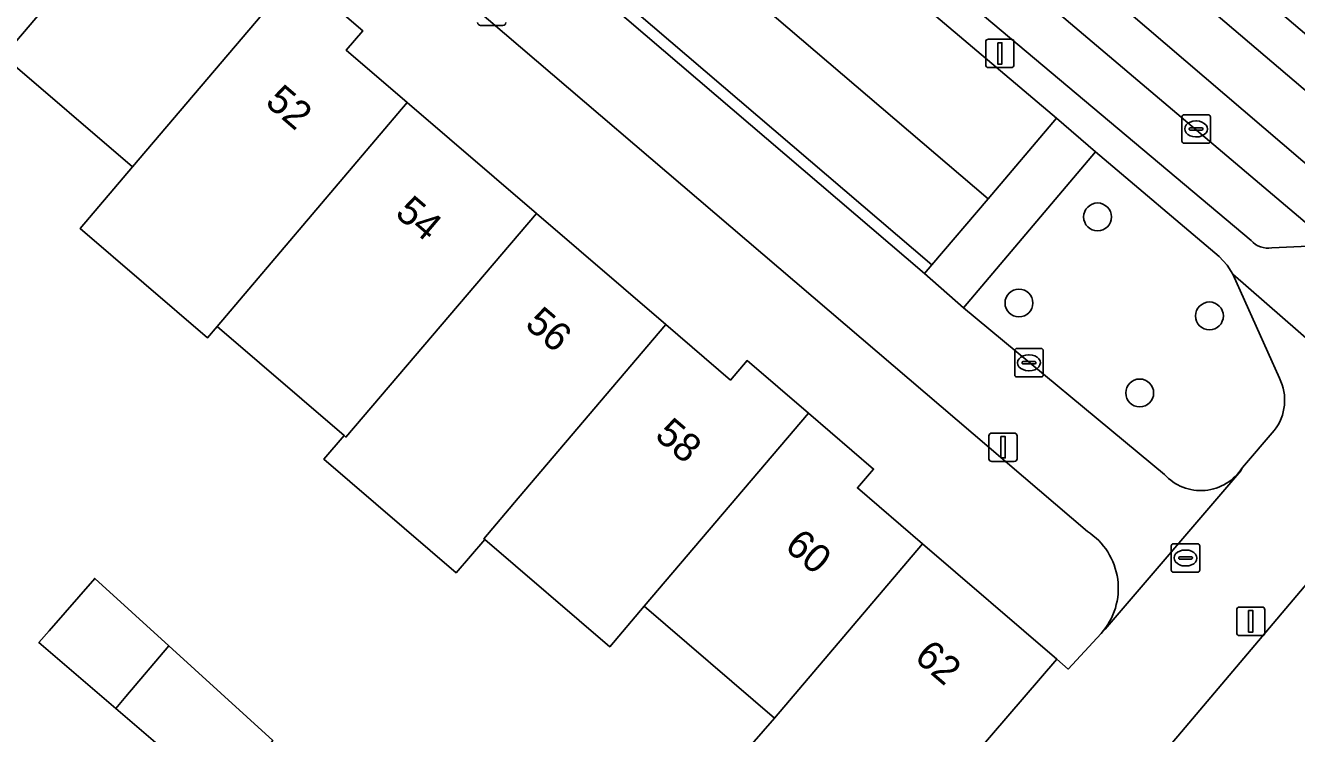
# Model space of a CAD drawing. Extents: x 162523 to 163266, y 381230 to 382050.
# Drawn here: x 163035.02 to 163079.66, y 381775.7 to 381800.56 of the extents above; entities that cross this region are included whole.
import ezdxf

# ---------------------------------------------------------------- set-up
doc = ezdxf.new("R2010")
doc.units = 0
for name, color, linetype in [('IMGEO_Boom', 7, 'Continuous'), ('IMGEO_Brandkraan', 7, 'Continuous'), ('IMGEO_Erf', 7, 'Continuous'), ('IMGEO_Groenvoorziening', 7, 'Continuous'), ('IMGEO_Haag', 7, 'Continuous'), ('IMGEO_Kolk', 7, 'Continuous'), ('IMGEO_Lichtmast', 7, 'Continuous'), ('IMGEO_Pand', 7, 'Continuous'), ('IMGEO_Pand_nummerreeks', 7, 'Continuous'), ('IMGEO_Parkeervlak_open', 7, 'Continuous'), ('IMGEO_Rijbaan_lokaal_gesloten', 7, 'Continuous'), ('IMGEO_Rijbaan_lokaal_open', 7, 'Continuous'), ('IMGEO_Verkeerseiland_gesloten', 7, 'Continuous'), ('IMGEO_Voetpad_open', 7, 'Continuous')]:
    doc.layers.add(name, color=color, linetype=linetype)

msp = doc.modelspace()

# ---------------------------------------------------------------- linework, layer by layer
at = {"layer": 'IMGEO_Boom'}
for centre in [(163072.674, 381793.839), (163069.913, 381790.816), (163076.605, 381790.363), (163074.155, 381787.658)]:
    msp.add_circle(centre, 0.489, dxfattribs=at)
at = {"layer": 'IMGEO_Brandkraan'}
for p, q in [((163075.339, 381782.364), (163076.191, 381782.364)), ((163075.264, 381781.438), (163075.264, 381782.29)), ((163075.566, 381781.907), (163075.964, 381781.907)), ((163075.752, 381782.144), (163075.777, 381782.144)), ((163076.265, 381782.29), (163076.265, 381781.438)), ((163075.523, 381781.858), (163075.523, 381781.87)), ((163075.961, 381781.821), (163075.563, 381781.821)), ((163075.775, 381781.584), (163075.75, 381781.584)), ((163076.007, 381781.87), (163076.007, 381781.858)), ((163076.191, 381781.364), (163075.339, 381781.364))]:
    msp.add_line(p, q, dxfattribs=at)
for points in [[(163075.339, 381782.364), (163076.191, 381782.364)], [(163075.264, 381781.438), (163075.264, 381782.29)], [(163076.265, 381782.29), (163076.265, 381781.438)], [(163076.191, 381781.364), (163075.339, 381781.364)]]:
    msp.add_lwpolyline(points, dxfattribs=at)
for centre, radius, start, end in [((163075.341, 381782.288), 0.0765, 91.552, 178.448), ((163075.341, 381782.288), 0.0765, 91.552, 178.448), ((163076.189, 381782.288), 0.0765, 1.552, 88.448), ((163076.189, 381782.288), 0.0765, 1.552, 88.448), ((163075.563, 381781.867), 0.0403, 85.8775, 175.7526), ((163075.968, 381781.869), 0.0386, 1.7309, 96.639), ((163075.56, 381781.857), 0.0366, 178.938, 274.7102), ((163075.964, 381781.864), 0.043, 264.8664, 352.4533), ((163075.341, 381781.44), 0.0765, 181.552, 268.448), ((163075.341, 381781.44), 0.0765, 181.552, 268.448), ((163076.189, 381781.44), 0.0765, 271.552, 358.448), ((163076.189, 381781.44), 0.0765, 271.552, 358.448)]:
    msp.add_arc(centre, radius, start, end, dxfattribs=at)
for centre, major_axis, ratio, start_param, end_param in [((163075.751, 381781.864), (-0.387, 0.002), 0.722429, 4.712389, 7.853982), ((163075.776, 381781.864), (-0.39, 0.002), 0.717154, 1.570796, 4.712389)]:
    msp.add_ellipse(centre, major_axis=major_axis, ratio=ratio, start_param=start_param, end_param=end_param, dxfattribs=at)
at = {"layer": 'IMGEO_Erf'}
for points in [[(163072.316, 381782.8), (163039.316, 381810.986)], [(163035.168, 381810.664), (163034.367, 381809.775), (163034.766, 381809.504), (163039.393, 381805.532), (163041.723, 381803.532), (163042.345, 381804.256), (163044.538, 381802.373), (163046.874, 381800.368), (163046.292, 381799.689), (163048.434, 381797.85), (163052.967, 381793.958), (163057.512, 381790.057), (163059.781, 381788.109), (163060.369, 381788.794), (163062.518, 381786.95), (163064.809, 381784.984), (163064.242, 381784.322), (163066.529, 381782.358), (163071.239, 381778.315), (163071.642, 381777.967), (163072.8, 381779.218)], [(163058.939, 381773.505), (163061.326, 381776.24), (163056.75, 381780.169), (163055.541, 381778.749), (163051.151, 381782.517), (163050.146, 381781.346), (163045.507, 381785.328), (163046.22, 381786.159), (163041.754, 381789.992), (163041.415, 381789.593), (163036.944, 381793.432), (163038.781, 381795.595), (163034.252, 381799.483)]]:
    msp.add_lwpolyline(points, dxfattribs=at)
msp.add_lwpolyline([(163038.196, 381776.584), (163035.497, 381778.894), (163035.853, 381779.304), (163037.456, 381781.149), (163040.061, 381778.777), (163043.708, 381775.457), (163041.97, 381773.351)], close=True, dxfattribs=at)
msp.add_arc((163071.021, 381780.801), 2.382, 318.3372, 57.0532, dxfattribs=at)
at = {"layer": 'IMGEO_Groenvoorziening'}
for points in [[(163071.233, 381797.302), (163053.446, 381812.343), (163051.086, 381809.632), (163068.827, 381794.472)], [(163068.827, 381794.472), (163051.086, 381809.632), (163049.09, 381807.34), (163066.858, 381792.157)], [(163066.858, 381792.157), (163049.09, 381807.34), (163048.827, 381807.038), (163066.599, 381791.852)]]:
    msp.add_lwpolyline(points, close=True, dxfattribs=at)
for points in [[(163079.06, 381788.177), (163077.42, 381791.832), (163077.226, 381792.149), (163076.943, 381792.45), (163072.604, 381796.126), (163067.968, 381790.65), (163075.022, 381784.8)], [(163077.759, 381785.04), (163078.877, 381786.336)]]:
    msp.add_lwpolyline(points, dxfattribs=at)
for centre, radius, start, end in [((163077.525, 381787.4), 1.721, 321.8026, 26.844), ((163076.3, 381785.957), 1.724, 222.167, 327.8556)]:
    msp.add_arc(centre, radius, start, end, dxfattribs=at)
at = {"layer": 'IMGEO_Haag'}
msp.add_lwpolyline([(163066.858, 381792.157), (163049.09, 381807.34), (163048.827, 381807.038), (163066.599, 381791.852)], close=True, dxfattribs=at)
at = {"layer": 'IMGEO_Kolk'}
for p, q in [((163075.634, 381796.5), (163075.634, 381797.352)), ((163075.709, 381797.426), (163076.561, 381797.426)), ((163076.122, 381797.206), (163076.147, 381797.206)), ((163076.635, 381797.352), (163076.635, 381796.5)), ((163075.893, 381796.92), (163075.893, 381796.932)), ((163076.331, 381796.883), (163075.933, 381796.883)), ((163075.936, 381796.969), (163076.334, 381796.969)), ((163076.145, 381796.646), (163076.12, 381796.646)), ((163076.377, 381796.932), (163076.377, 381796.92)), ((163076.561, 381796.426), (163075.709, 381796.426)), ((163069.764, 381788.293), (163069.764, 381789.145)), ((163069.839, 381789.219), (163070.691, 381789.219)), ((163070.765, 381789.145), (163070.765, 381788.293)), ((163070.023, 381788.713), (163070.023, 381788.725)), ((163070.461, 381788.676), (163070.063, 381788.676)), ((163070.066, 381788.762), (163070.464, 381788.762)), ((163070.252, 381788.999), (163070.277, 381788.999)), ((163070.507, 381788.725), (163070.507, 381788.713)), ((163070.691, 381788.219), (163069.839, 381788.219)), ((163070.275, 381788.439), (163070.25, 381788.439))]:
    msp.add_line(p, q, dxfattribs=at)
for points in [[(163075.634, 381796.5), (163075.634, 381797.352)], [(163075.709, 381797.426), (163076.561, 381797.426)], [(163076.635, 381797.352), (163076.635, 381796.5)], [(163076.561, 381796.426), (163075.709, 381796.426)], [(163069.764, 381788.293), (163069.764, 381789.145)], [(163069.839, 381789.219), (163070.691, 381789.219)], [(163070.765, 381789.145), (163070.765, 381788.293)], [(163070.691, 381788.219), (163069.839, 381788.219)]]:
    msp.add_lwpolyline(points, dxfattribs=at)
for centre, radius, start, end in [((163075.711, 381797.35), 0.0765, 91.552, 178.448), ((163075.711, 381797.35), 0.0765, 91.552, 178.448), ((163076.559, 381797.35), 0.0765, 1.552, 88.448), ((163076.559, 381797.35), 0.0765, 1.552, 88.448), ((163075.933, 381796.929), 0.0403, 85.8775, 175.7526), ((163075.93, 381796.919), 0.0366, 178.938, 274.7102), ((163076.334, 381796.926), 0.043, 264.8664, 352.4533), ((163076.338, 381796.931), 0.0386, 1.7309, 96.639), ((163075.711, 381796.502), 0.0765, 181.552, 268.448), ((163075.711, 381796.502), 0.0765, 181.552, 268.448), ((163076.559, 381796.502), 0.0765, 271.552, 358.448), ((163076.559, 381796.502), 0.0765, 271.552, 358.448), ((163069.841, 381789.143), 0.0765, 91.552, 178.448), ((163069.841, 381789.143), 0.0765, 91.552, 178.448), ((163070.689, 381789.143), 0.0765, 1.552, 88.448), ((163070.689, 381789.143), 0.0765, 1.552, 88.448), ((163070.063, 381788.722), 0.0403, 85.8775, 175.7526), ((163070.06, 381788.712), 0.0366, 178.938, 274.7102), ((163070.464, 381788.719), 0.043, 264.8664, 352.4533), ((163070.468, 381788.724), 0.0386, 1.7309, 96.639), ((163069.841, 381788.295), 0.0765, 181.552, 268.448), ((163069.841, 381788.295), 0.0765, 181.552, 268.448), ((163070.689, 381788.295), 0.0765, 271.552, 358.448), ((163070.689, 381788.295), 0.0765, 271.552, 358.448)]:
    msp.add_arc(centre, radius, start, end, dxfattribs=at)
for centre, major_axis, ratio, start_param, end_param in [((163076.121, 381796.926), (-0.387, 0.002), 0.722429, 4.712389, 7.853982), ((163076.146, 381796.926), (-0.39, 0.002), 0.717154, 1.570796, 4.712389), ((163070.251, 381788.719), (-0.387, 0.002), 0.722429, 4.712389, 7.853982), ((163070.276, 381788.719), (-0.39, 0.002), 0.717154, 1.570796, 4.712389)]:
    msp.add_ellipse(centre, major_axis=major_axis, ratio=ratio, start_param=start_param, end_param=end_param, dxfattribs=at)
at = {"layer": 'IMGEO_Lichtmast'}
for p, q in [((163051.794, 381800.56), (163051.004, 381800.56)), ((163051.004, 381800.56), (163051.794, 381800.56)), ((163068.747, 381799.179), (163068.747, 381799.979)), ((163068.747, 381799.979), (163068.747, 381799.179)), ((163068.847, 381800.079), (163069.637, 381800.079)), ((163069.637, 381800.079), (163068.847, 381800.079)), ((163069.737, 381799.979), (163069.737, 381799.179)), ((163069.737, 381799.179), (163069.737, 381799.979)), ((163069.637, 381799.079), (163068.847, 381799.079)), ((163068.847, 381799.079), (163069.637, 381799.079)), ((163068.861, 381785.35), (163068.861, 381786.15)), ((163068.861, 381786.15), (163068.861, 381785.35)), ((163068.961, 381786.25), (163069.751, 381786.25)), ((163069.751, 381786.25), (163068.961, 381786.25)), ((163069.851, 381786.15), (163069.851, 381785.35)), ((163069.851, 381785.35), (163069.851, 381786.15)), ((163069.751, 381785.25), (163068.961, 381785.25)), ((163068.961, 381785.25), (163069.751, 381785.25)), ((163077.66, 381780.141), (163078.45, 381780.141)), ((163078.45, 381780.141), (163077.66, 381780.141)), ((163077.56, 381779.241), (163077.56, 381780.041)), ((163077.56, 381780.041), (163077.56, 381779.241)), ((163078.55, 381780.041), (163078.55, 381779.241)), ((163078.55, 381779.241), (163078.55, 381780.041)), ((163078.45, 381779.141), (163077.66, 381779.141)), ((163077.66, 381779.141), (163078.45, 381779.141))]:
    msp.add_line(p, q, dxfattribs=at)
for points in [[(163069.167, 381799.954), (163069.317, 381799.954), (163069.317, 381799.204), (163069.167, 381799.204), (163069.167, 381799.954)], [(163069.281, 381786.125), (163069.431, 381786.125), (163069.431, 381785.375), (163069.281, 381785.375), (163069.281, 381786.125)], [(163077.98, 381780.016), (163078.13, 381780.016), (163078.13, 381779.266), (163077.98, 381779.266), (163077.98, 381780.016)]]:
    msp.add_lwpolyline(points, dxfattribs=at)
for centre, start, end in [((163051.004, 381800.66), 180, 270), ((163051.004, 381800.66), 180, 270), ((163051.794, 381800.66), 270, 0), ((163051.794, 381800.66), 270, 0), ((163068.847, 381799.979), 90, 180), ((163068.847, 381799.979), 90, 180), ((163069.637, 381799.979), 0, 90), ((163069.637, 381799.979), 360, 90), ((163068.847, 381799.179), 180, 270), ((163068.847, 381799.179), 180, 270), ((163069.637, 381799.179), 270, 0), ((163069.637, 381799.179), 270, 0), ((163068.961, 381786.15), 90, 180), ((163068.961, 381786.15), 90, 180), ((163069.751, 381786.15), 0, 90), ((163069.751, 381786.15), 360, 90), ((163068.961, 381785.35), 180, 270), ((163068.961, 381785.35), 180, 270), ((163069.751, 381785.35), 270, 0), ((163069.751, 381785.35), 270, 0), ((163077.66, 381780.041), 90, 180), ((163077.66, 381780.041), 90, 180), ((163078.45, 381780.041), 0, 90), ((163078.45, 381780.041), 360, 90), ((163077.66, 381779.241), 180, 270), ((163077.66, 381779.241), 180, 270), ((163078.45, 381779.241), 270, 0), ((163078.45, 381779.241), 270, 0)]:
    msp.add_arc(centre, 0.1, start, end, dxfattribs=at)
at = {"layer": 'IMGEO_Pand'}
for points in [[(163039.393, 381805.532), (163034.766, 381809.504), (163029.714, 381803.618), (163029.596, 381803.48), (163034.252, 381799.483)], [(163039.393, 381805.532), (163034.252, 381799.483), (163038.781, 381795.595), (163044.538, 381802.373), (163042.345, 381804.256), (163041.723, 381803.532)], [(163048.434, 381797.85), (163046.292, 381799.689), (163046.874, 381800.368), (163044.538, 381802.373), (163038.781, 381795.595), (163036.944, 381793.432), (163041.415, 381789.593), (163041.754, 381789.992)], [(163052.967, 381793.958), (163048.434, 381797.85), (163041.754, 381789.992), (163046.22, 381786.159), (163046.279, 381786.108)], [(163057.512, 381790.057), (163052.967, 381793.958), (163046.279, 381786.108), (163046.22, 381786.159), (163045.507, 381785.328), (163050.146, 381781.346), (163051.151, 381782.517), (163051.123, 381782.541), (163052.331, 381783.962)], [(163062.518, 381786.95), (163060.369, 381788.794), (163059.781, 381788.109), (163057.512, 381790.057), (163052.331, 381783.962), (163051.123, 381782.541), (163051.151, 381782.517), (163055.541, 381778.749), (163056.75, 381780.169)], [(163056.75, 381780.169), (163061.326, 381776.24), (163066.529, 381782.358), (163064.242, 381784.322), (163064.809, 381784.984), (163062.518, 381786.95)], [(163058.939, 381773.505), (163064.046, 381769.103), (163066.393, 381771.873), (163066.007, 381772.222), (163071.239, 381778.315), (163066.529, 381782.358), (163061.326, 381776.24)], [(163037.456, 381781.149), (163035.853, 381779.304), (163035.497, 381778.894), (163038.196, 381776.584), (163038.547, 381776.997), (163040.061, 381778.777)], [(163040.061, 381778.777), (163038.547, 381776.997), (163038.196, 381776.584), (163041.97, 381773.351), (163043.708, 381775.457)]]:
    msp.add_lwpolyline(points, close=True, dxfattribs=at)
at = {"layer": 'IMGEO_Parkeervlak_open'}
for points in [[(163081.528, 381792.334), (163080.88, 381792.883), (163049.97, 381819.047), (163049.325, 381819.592)], [(163050.564, 381816.117), (163078.066, 381793.005)], [(163078.793, 381792.751), (163080.082, 381792.811)]]:
    msp.add_lwpolyline(points, dxfattribs=at)
msp.add_arc((163078.668, 381793.559), 0.818, 222.6591, 278.824, dxfattribs=at)
at = {"layer": 'IMGEO_Rijbaan_lokaal_gesloten'}
for points in [[(163084.88, 381797.542), (163077.279, 381804.065), (163053.906, 381823.577), (163053.906, 381823.577), (163053.344, 381822.93), (163055.404, 381821.166), (163082.143, 381798.414), (163084.143, 381796.698), (163084.88, 381797.542)], [(163081.228, 381797.213), (163054.445, 381820.01), (163052.361, 381821.799), (163051.125, 381820.377), (163081.895, 381794.076), (163083.169, 381795.572)], [(163080.88, 381792.883), (163081.895, 381794.076), (163051.125, 381820.377), (163049.97, 381819.047)]]:
    msp.add_lwpolyline(points, close=True, dxfattribs=at)
at = {"layer": 'IMGEO_Rijbaan_lokaal_open'}
msp.add_lwpolyline([(163082.006, 381773.88), (163082.071, 381774.015), (163082.17, 381774.133), (163082.504, 381774.529), (163084.856, 381777.318), (163080.187, 381781.159), (163077.938, 381778.496), (163076.781, 381777.126), (163063.43, 381761.353), (163061.032, 381758.524), (163053.818, 381750), (163052.736, 381748.714), (163057.384, 381744.751), (163061.893, 381750)], close=True, dxfattribs=at)
at = {"layer": 'IMGEO_Verkeerseiland_gesloten'}
for points in [[(163046.837, 381826.53), (163049.953, 381823.903), (163052.082, 381822.038), (163052.361, 381821.799), (163054.445, 381820.01), (163081.228, 381797.213), (163083.169, 381795.572), (163086.59, 381792.678)], [(163085.957, 381795.141), (163084.143, 381796.698), (163082.143, 381798.414), (163055.404, 381821.166), (163053.344, 381822.93), (163053.015, 381823.212), (163050.857, 381825.064), (163049.366, 381826.322)]]:
    msp.add_lwpolyline(points, dxfattribs=at)
at = {"layer": 'IMGEO_Voetpad_open'}
for points in [[(163039.444, 381823.884), (163047.506, 381817.271), (163047.578, 381817.213), (163047.649, 381817.154), (163052.049, 381813.517), (163053.446, 381812.343), (163071.233, 381797.302), (163072.604, 381796.126), (163076.943, 381792.45), (163077.226, 381792.149), (163077.42, 381791.832), (163083.755, 381786.308)], [(163078.066, 381793.005), (163050.564, 381816.117)], [(163075.022, 381784.8), (163067.968, 381790.65), (163066.599, 381791.852), (163048.827, 381807.038), (163047.469, 381808.16), (163040.533, 381813.985)], [(163039.316, 381810.986), (163072.316, 381782.8)], [(163080.082, 381792.811), (163078.793, 381792.751)], [(163083.755, 381786.308), (163077.42, 381791.832), (163079.06, 381788.177)], [(163078.877, 381786.336), (163077.759, 381785.04), (163077.709, 381784.926), (163072.943, 381779.361), (163072.8, 381779.218), (163071.642, 381777.967), (163071.239, 381778.315), (163066.007, 381772.222), (163066.393, 381771.873), (163064.046, 381769.103), (163059.733, 381763.949), (163057.544, 381761.374), (163056.336, 381759.96), (163057.405, 381759.019), (163049.821, 381750), (163000, 381690.752), (162988.098, 381676.598), (162985.004, 381672.854)], [(163072.8, 381779.218), (163072.943, 381779.361), (163077.709, 381784.926), (163077.759, 381785.04)], [(163050.901, 381746.533), (163052.736, 381748.714), (163053.818, 381750), (163061.032, 381758.524), (163060.239, 381759.196), (163062.637, 381762.025), (163063.43, 381761.353), (163076.781, 381777.126), (163077.938, 381778.496), (163080.187, 381781.159), (163080.943, 381782.054), (163082.507, 381783.885)]]:
    msp.add_lwpolyline(points, dxfattribs=at)
msp.add_lwpolyline([(163067.968, 381790.65), (163072.604, 381796.126), (163071.233, 381797.302), (163068.827, 381794.472), (163066.858, 381792.157), (163066.599, 381791.852)], close=True, dxfattribs=at)
for centre, radius, start, end in [((163078.668, 381793.559), 0.818, 222.6591, 278.824), ((163077.525, 381787.4), 1.721, 321.8026, 26.844), ((163076.3, 381785.957), 1.724, 222.167, 327.8556), ((163071.021, 381780.801), 2.382, 318.3372, 57.0532)]:
    msp.add_arc(centre, radius, start, end, dxfattribs=at)

# ---------------------------------------------------------------- texts
at = {"layer": 'IMGEO_Pand_nummerreeks'}
for s, rotation, p in [('52', 319.4632, (163043.402, 381797.803)), ('54', 319.4632, (163047.963, 381793.903)), ('56', 319.4632, (163052.522, 381790.004)), ('58', 319.4632, (163057.083, 381786.104)), ('60', 319.4654, (163061.643, 381782.205)), ('62', 319.4654, (163066.198, 381778.31))]:
    msp.add_text(s, height=1, rotation=rotation, dxfattribs=at).set_placement(p)

doc.saveas('drawing.dxf')
